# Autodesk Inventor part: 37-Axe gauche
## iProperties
Created: 2011-02
Part Number: 37-Axe gauche
Document SubType Name: Modeling
Designer: eric
Density: 1 g/cm^3
Author: eric
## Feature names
1. Base1
